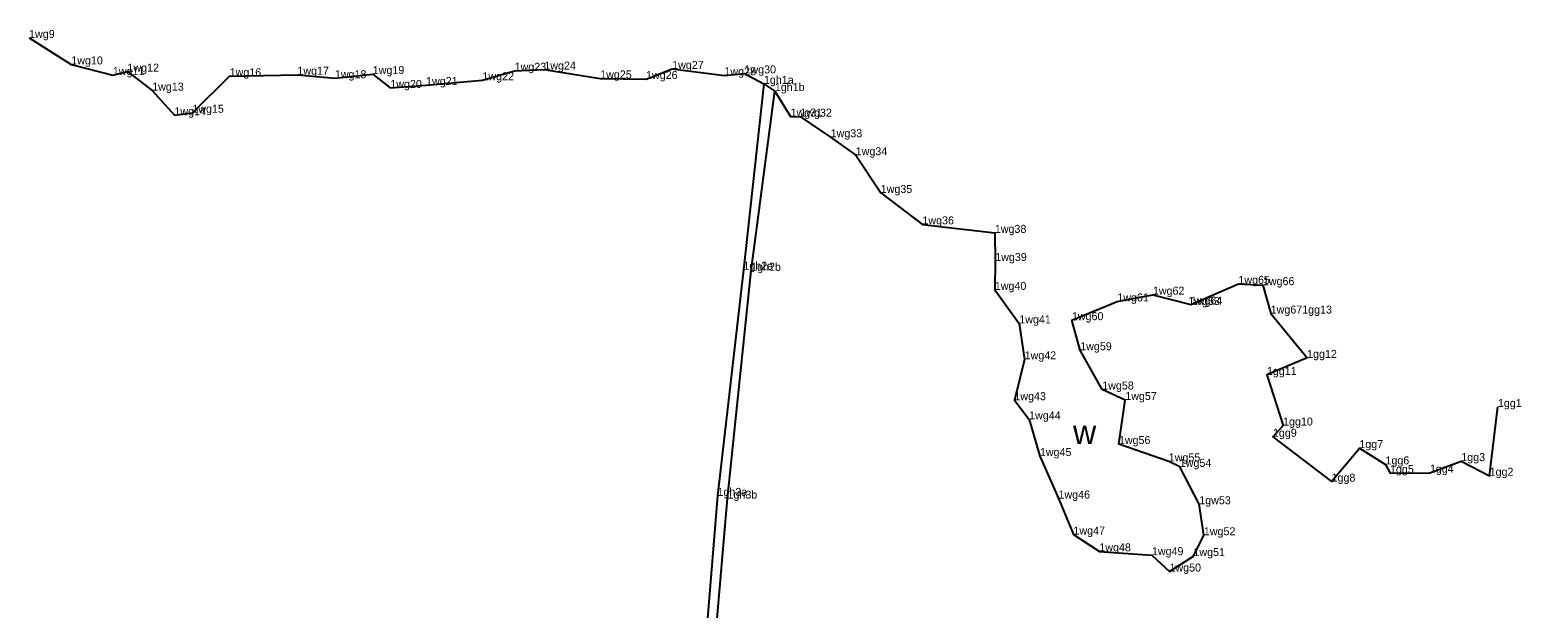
# Model space of a CAD drawing. Extents: x 2072529 to 2267990, y 436423 to 470008.
# Drawn here: x 2077728 to 2078660, y 466151 to 466512 of the extents above; entities that cross this region are included whole.
import ezdxf

# ---------------------------------------------------------------- set-up
doc = ezdxf.new("R2010")
doc.units = 0
for name, color, linetype in [('Level 3', 7, 'Continuous'), ('Old_Level_52', 7, 'Continuous'), ('Prop SS Cut Line', 7, 'Continuous')]:
    doc.layers.add(name, color=color, linetype=linetype)

msp = doc.modelspace()

# ---------------------------------------------------------------- linework, layer by layer
at = {"layer": 'Level 3'}
for p, q in [((2077754.339, 466490.591), (2077754.339, 466490.591)), ((2077780.327, 466483.888), (2077780.327, 466483.888)), ((2077789.456, 466486.053), (2077789.456, 466486.053)), ((2077853.309, 466483.162), (2077853.309, 466483.162)), ((2077895.657, 466484.138), (2077895.657, 466484.138)), ((2077919.067, 466481.96), (2077919.067, 466481.96)), ((2077942.748, 466484.559), (2077942.748, 466484.559)), ((2078011.301, 466480.697), (2078011.301, 466480.697)), ((2078031.407, 466486.61), (2078031.407, 466486.61)), ((2078049.961, 466487.348), (2078049.961, 466487.348)), ((2078084.877, 466481.812), (2078084.877, 466481.812)), ((2078113.505, 466481.452), (2078113.505, 466481.452)), ((2078129.863, 466487.752), (2078129.863, 466487.752)), ((2078162.544, 466483.745), (2078162.544, 466483.745)), ((2078175.045, 466484.952), (2078175.045, 466484.952)), ((2077804.913, 466474.191), (2077804.913, 466474.191)), ((2077953.696, 466475.857), (2077953.696, 466475.857)), ((2077976.06, 466477.674), (2077976.06, 466477.674)), ((2078187.207, 466478.434), (2078187.207, 466478.434)), ((2078194.015, 466473.907), (2078194.015, 466473.907)), ((2077818.794, 466458.784), (2077818.794, 466458.784)), ((2077829.993, 466460.363), (2077829.993, 466460.363)), ((2078203.848, 466457.951), (2078203.848, 466457.951)), ((2078209.968, 466457.902), (2078209.968, 466457.902)), ((2078228.902, 466445.021), (2078228.902, 466445.021)), ((2078244.557, 466433.776), (2078244.557, 466433.776)), ((2078260.193, 466410.189), (2078260.193, 466410.189)), ((2078286.245, 466390.562), (2078286.245, 466390.562)), ((2078331.503, 466385.247), (2078331.503, 466385.247)), ((2078331.743, 466367.661), (2078331.743, 466367.661)), ((2078174.376, 466362.169), (2078174.376, 466362.169)), ((2078179.216, 466361.517), (2078179.216, 466361.517)), ((2078331.496, 466349.591), (2078331.496, 466349.591)), ((2078483.701, 466353.355), (2078483.701, 466353.355)), ((2078499.018, 466352.524), (2078499.018, 466352.524)), ((2078408.043, 466342.358), (2078408.043, 466342.358)), ((2078430.278, 466346.593), (2078430.278, 466346.593)), ((2078452.411, 466340.162), (2078452.411, 466340.162)), ((2078453.974, 466340.433), (2078453.974, 466340.433)), ((2078379.66, 466330.642), (2078379.66, 466330.642)), ((2078503.883, 466334.766), (2078503.883, 466334.766)), ((2078346.769, 466328.634), (2078346.769, 466328.634)), ((2078384.855, 466311.837), (2078384.855, 466311.837)), ((2078350.124, 466306.158), (2078350.124, 466306.158)), ((2078526.657, 466307.071), (2078526.657, 466307.071)), ((2078501.524, 466296.378), (2078501.524, 466296.378)), ((2078398.619, 466287.287), (2078398.619, 466287.287)), ((2078343.722, 466280.609), (2078343.722, 466280.609)), ((2078412.993, 466280.709), (2078412.993, 466280.709)), ((2078645.877, 466276.357), (2078645.877, 466276.357)), ((2078352.938, 466268.622), (2078352.938, 466268.622)), ((2078505.302, 466257.733), (2078505.302, 466257.733)), ((2078511.628, 466264.771), (2078511.628, 466264.771)), ((2078409.028, 466253.182), (2078409.028, 466253.182)), ((2078559.306, 466250.672), (2078559.306, 466250.672)), ((2078359.654, 466245.681), (2078359.654, 466245.681)), ((2078440.214, 466242.347), (2078440.214, 466242.347)), ((2078447.084, 466238.917), (2078447.084, 466238.917)), ((2078575.617, 466240.472), (2078575.617, 466240.472)), ((2078623.014, 466242.534), (2078623.014, 466242.534)), ((2078541.943, 466229.718), (2078541.943, 466229.718)), ((2078578.457, 466235.03), (2078578.457, 466235.03)), ((2078603.386, 466235.274), (2078603.386, 466235.274)), ((2078640.73, 466233.35), (2078640.73, 466233.35)), ((2078158.18, 466220.774), (2078158.18, 466220.774)), ((2078164.441, 466219.076), (2078164.441, 466219.076)), ((2078371.274, 466219.099), (2078371.274, 466219.099)), ((2078459.238, 466215.548), (2078459.238, 466215.548)), ((2078380.635, 466196.563), (2078380.635, 466196.563)), ((2078462.125, 466196.13), (2078462.125, 466196.13)), ((2078396.815, 466186.08), (2078396.815, 466186.08)), ((2078429.669, 466183.704), (2078429.669, 466183.704)), ((2078455.603, 466183.131), (2078455.603, 466183.131)), ((2078440.642, 466173.47), (2078440.642, 466173.47))]:
    msp.add_line(p, q, dxfattribs=at)
at = {"layer": 'Old_Level_52'}
for points in [[(2077727.975, 466507.145), (2077754.339, 466490.591), (2077780.327, 466483.888), (2077789.456, 466486.053), (2077804.913, 466474.191), (2077818.794, 466458.784), (2077829.993, 466460.363), (2077853.309, 466483.162), (2077895.657, 466484.138), (2077919.067, 466481.96), (2077942.748, 466484.559), (2077953.696, 466475.857), (2077976.06, 466477.674), (2078011.301, 466480.697), (2078031.407, 466486.61), (2078049.961, 466487.348), (2078084.877, 466481.812), (2078113.505, 466481.452), (2078129.863, 466487.752), (2078162.544, 466483.745), (2078175.045, 466484.952), (2078187.207, 466478.434), (2078194.015, 466473.907), (2078203.848, 466457.951), (2078209.968, 466457.902), (2078228.902, 466445.021), (2078244.557, 466433.776), (2078260.193, 466410.189), (2078286.245, 466390.562), (2078331.503, 466385.247), (2078331.743, 466367.661), (2078331.496, 466349.591), (2078346.769, 466328.634), (2078350.124, 466306.158), (2078343.722, 466280.609), (2078352.938, 466268.622), (2078359.654, 466245.681), (2078371.274, 466219.099), (2078380.635, 466196.563), (2078396.815, 466186.08), (2078429.669, 466183.704), (2078440.642, 466173.47), (2078455.603, 466183.131), (2078462.125, 466196.13), (2078459.238, 466215.548), (2078447.084, 466238.917), (2078440.214, 466242.347), (2078409.028, 466253.182), (2078412.993, 466280.709), (2078398.619, 466287.287), (2078384.855, 466311.837), (2078379.66, 466330.642), (2078408.043, 466342.358)], [(2078187.207, 466478.434), (2078174.376, 466362.169), (2078158.18, 466220.774), (2078147.017, 466082.829), (2078142.832, 465971.82), (2078137.396, 465936.903), (2078115.034, 465901.653), (2078045.501, 465848.946), (2078008.251, 465812.431), (2078013.504, 465803.681), (2078049.793, 465845.457), (2078119.546, 465896.835), (2078141.846, 465931.823), (2078148.473, 465973.539), (2078152.623, 466081.039), (2078164.441, 466219.076), (2078179.216, 466361.517), (2078194.015, 466473.907)], [(2078408.043, 466342.358), (2078430.278, 466346.593), (2078453.974, 466340.433), (2078453.974, 466340.433), (2078483.701, 466353.355), (2078499.018, 466352.524), (2078503.883, 466334.766)], [(2078503.883, 466334.766), (2078526.657, 466307.071), (2078501.524, 466296.378), (2078511.628, 466264.771), (2078505.302, 466257.733), (2078541.943, 466229.718), (2078559.306, 466250.672), (2078575.617, 466240.472), (2078578.457, 466235.03), (2078603.386, 466235.274), (2078623.014, 466242.534), (2078640.73, 466233.35), (2078645.877, 466276.357)]]:
    msp.add_lwpolyline(points, dxfattribs=at)

# ---------------------------------------------------------------- texts
for s, p in [('1wg9', (2077727.975, 466507.145)), ('1wg10', (2077754.339, 466490.591)), ('1wg11', (2077780.327, 466483.888)), ('1wg12', (2077789.456, 466486.053)), ('1wg17', (2077895.657, 466484.138)), ('1wg19', (2077942.748, 466484.559)), ('1wg23', (2078031.407, 466486.61)), ('1wg24', (2078049.961, 466487.348)), ('1wg27', (2078129.863, 466487.752)), ('1wg28', (2078162.544, 466483.745)), ('1wg30', (2078175.045, 466484.952)), ('1wg13', (2077804.913, 466474.191)), ('1wg16', (2077853.309, 466483.162)), ('1wg18', (2077919.067, 466481.96)), ('1wg20', (2077953.696, 466475.857)), ('1wg21', (2077976.06, 466477.674)), ('1wg22', (2078011.301, 466480.697)), ('1wg25', (2078084.877, 466481.812)), ('1wg26', (2078113.505, 466481.452)), ('1gh1a', (2078187.207, 466478.434)), ('1gh1b', (2078194.015, 466473.907)), ('1wg14', (2077818.794, 466458.784)), ('1wg15', (2077829.993, 466460.363)), ('1wg31', (2078203.848, 466457.951)), ('1wg32', (2078209.968, 466457.902)), ('1wg33', (2078228.902, 466445.021)), ('1wg34', (2078244.557, 466433.776)), ('1wg35', (2078260.193, 466410.189)), ('1wg36', (2078286.245, 466390.562)), ('1wg38', (2078331.503, 466385.247)), ('1gh2a', (2078174.376, 466362.169)), ('1wg39', (2078331.743, 466367.661)), ('1gh2b', (2078179.216, 466361.517)), ('1wg65', (2078483.701, 466353.355)), ('1wg40', (2078331.496, 466349.591)), ('1wg62', (2078430.278, 466346.593)), ('1wg66', (2078499.018, 466352.524)), ('1wg61', (2078408.043, 466342.358)), ('1wg63', (2078452.411, 466340.162)), ('1wg64', (2078453.974, 466340.433)), ('1wg671gg13', (2078503.883, 466334.766)), ('1wg41', (2078346.769, 466328.634)), ('1wg60', (2078379.66, 466330.642)), ('1wg59', (2078384.855, 466311.837)), ('1gg12', (2078526.657, 466307.071)), ('1wg42', (2078350.124, 466306.158)), ('1gg11', (2078501.524, 466296.378)), ('1wg43', (2078343.722, 466280.609)), ('1wg58', (2078398.619, 466287.287)), ('1wg57', (2078412.993, 466280.709)), ('1gg1', (2078645.877, 466276.357)), ('1wg44', (2078352.938, 466268.622)), ('1gg10', (2078511.628, 466264.771)), ('1wg56', (2078409.028, 466253.182)), ('1gg9', (2078505.302, 466257.733)), ('1gg7', (2078559.306, 466250.672)), ('1wg45', (2078359.654, 466245.681)), ('1wg55', (2078440.214, 466242.347)), ('1gg3', (2078623.014, 466242.534)), ('1wg54', (2078447.084, 466238.917)), ('1gg6', (2078575.617, 466240.472)), ('1gg5', (2078578.457, 466235.03)), ('1gg4', (2078603.386, 466235.274)), ('1gg2', (2078640.73, 466233.35)), ('1gg8', (2078541.943, 466229.718)), ('1gh3a', (2078158.18, 466220.774)), ('1gh3b', (2078164.441, 466219.076)), ('1wg46', (2078371.274, 466219.099)), ('1gw53', (2078459.238, 466215.548)), ('1wg47', (2078380.635, 466196.563)), ('1wg52', (2078462.125, 466196.13)), ('1wg48', (2078396.815, 466186.08)), ('1wg49', (2078429.669, 466183.704)), ('1wg51', (2078455.603, 466183.131)), ('1wg50', (2078440.642, 466173.47))]:
    msp.add_text(s, height=5).set_placement(p)
at = {"layer": 'Prop SS Cut Line'}
msp.add_text('w', height=15, dxfattribs=at).set_placement((2078380.367, 466253.165))

doc.saveas('drawing.dxf')
